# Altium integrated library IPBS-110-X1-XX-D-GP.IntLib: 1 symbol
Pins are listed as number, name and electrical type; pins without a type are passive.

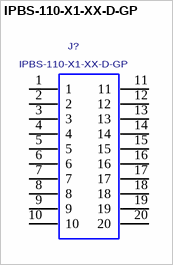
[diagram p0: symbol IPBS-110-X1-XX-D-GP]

## IPBS-110-X1-XX-D-GP
designator J?
0.165" DOUBLE ROW SOCKET ASSEMBLY.; MANUFACTURER: SAMTEC
footprint IPBS-110-X1-XX-D-GP
pins: 1, 2, 3, 4, 5, 6, 7, 8, 9, 10, 11, 12, 13, 14, 15, 16, 17, 18, 19, 20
